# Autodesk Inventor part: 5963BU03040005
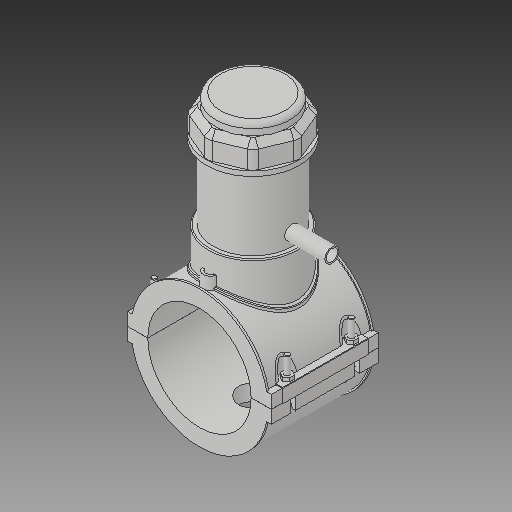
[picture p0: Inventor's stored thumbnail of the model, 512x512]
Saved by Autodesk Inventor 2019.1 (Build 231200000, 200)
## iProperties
Created: 2017-07
Part Number: 5963BU03040005
Material: Generic
Description: PLASSON TAPPING SADDLE 4''IPS x 1 1/2''CTS
Document SubType Name: Modeling
Designer: KIM
Mass: 1712.7 g
Surface Area: 2671.49 cm^2
Volume: 1712.7 cm^3
Density: 1 g/cm^3
Appearance: Default
Author: KIM
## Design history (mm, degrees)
derived "5963B.ipt"
feature "Solid1::5963B.ipt"
feature "Solid2::5963B.ipt"
feature "Solid4::5963B.ipt"
feature "Solid5::5963B.ipt"
tag "TaggingFeature1"
body "Solid1"
body "Solid2"
other parameters: "d0" = 114.1, "d2" = 159.004, "d3" = 28.525, "d4" = 118.11, "d5" = 0, "d6" = 0.1, "d8" = 0, "d19" = 6, "d20" = 6, "d21" = 70.866, "d23" = 0, "d24" = 35.433, "d26" = 0, "d29" = 3, "d30" = 38.03333, "d31" = 6, "d32" = 0, "d33" = 0, "d34" = 0.6, "d40" = 77.1316, "d41" = 102.69, "d43" = 0, "d45" = 0, "d47" = 145.031, "d70" = 15, "d72" = 0, "d73" = 6, "d75" = 5, "d76" = 0, "d77" = 5.705, "d78" = 87.05, "d79" = 15, "d80" = 47.244, "d82" = 5 deg, "d84" = 4, "d85" = 14, "d86" = 0, "d87" = 3, "d88" = 0, "d89" = 1, "d90" = 1, "d91" = 94.488, "d92" = 0, "d93" = 0.5, "d94" = 60.05263, "d96" = 151.2966, "d97" = 2.3622, "d98" = 0, "d102" = 1.141, "d120" = 140 deg, "d121" = 24.228, "d122" = 20 deg, "d123" = 296.66, "d124" = 88.998, "d126" = 0, "d143" = 117.523, "d145" = 26.33077, "d149" = 1.7115, "d150" = 28.96385, "d153" = 118.11, "d154" = 0, "d156" = 74.165, "d157" = 160 deg, "d159" = 6.846, "d161" = 1.7115, "d162" = 70.866, "d163" = 0, "d164" = 57.05, "d167" = 11.41, "d168" = 72.3561, "d170" = 3.2805, "d172" = 0, "d173" = 1, "d175" = 57.05, "d176" = 20 deg, "d177" = 7.987, "d178" = 34.23, "d180" = 0, "d183" = 13.692, "d184" = 6.3896, "d185" = 38.38575, "d186" = 38.38575, "d187" = 74.165, "d188" = 10.269, "d189" = 7.987, "d190" = 0, "d191" = 111.2475, "d193" = 6.1236, "d194" = 4.13385, "d195" = 90 deg, "d197" = 0, "d199" = 0, "d200" = 17.115, "d202" = 0, "d203" = 177.038, "d204" = 97.5555, "d205" = 71.883, "d206" = 87.2865, "d207" = 132.7785, "d208" = 138.08964, "d209" = 164.64534, "d210" = 88.3134, "d211" = 102.69, "d212" = 82.152, "d213" = 51.4116, "d216" = 0, "d217" = 11.41, "d218" = 5.705, "d219" = 1.141, "d222" = 114.1, "d224" = 0, "d230" = 6.846, "d233" = 6, "d236" = 79.502, "d237" = 35.433, "d238" = 6.02433, "d240" = 35.433, "d241" = 35.433, "d242" = 35.433, "d243" = 6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
